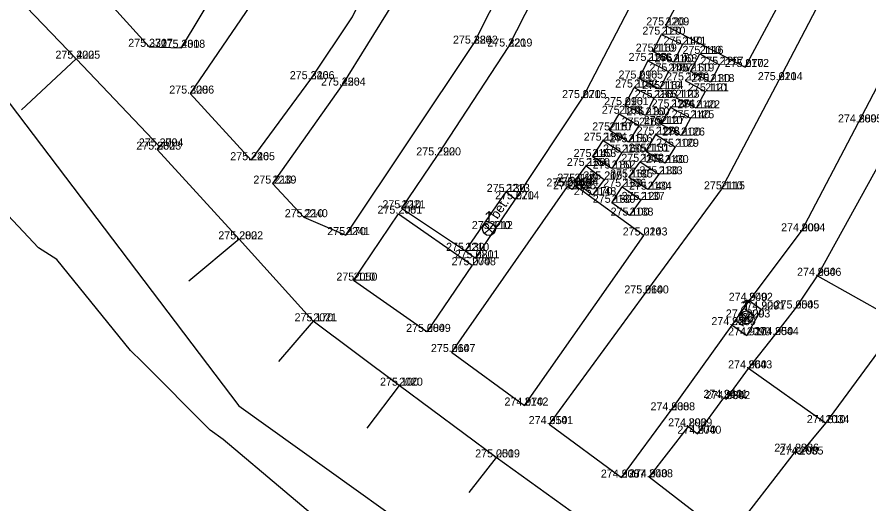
# Model space of a CAD drawing. Extents: x -776701 to -776081, y -974398 to -973771.
# Drawn here: x -776439.32 to -776412.71, y -974187.69 to -974172.49 of the extents above; entities that cross this region are included whole.
import ezdxf

# ---------------------------------------------------------------- set-up
doc = ezdxf.new("R2010")
doc.units = 0
for name, color, linetype in [('1 Body-bod', 7, 'Continuous'), ('10 Silnice-chodniky', 7, 'Continuous'), ('11 Rozhrani-nezpev zpev schody', 7, 'Continuous'), ('2 Body-cislo', 7, 'Continuous'), ('3 Body-vyska', 7, 'Continuous'), ('40 Popis-povrch', 7, 'Continuous'), ('58 Mobiliar', 7, 'Continuous'), ('7 Ploty', 7, 'Continuous'), ('Hranice parcel', 7, 'Continuous')]:
    doc.layers.add(name, color=color, linetype=linetype)

msp = doc.modelspace()

# ---------------------------------------------------------------- linework, layer by layer
at = {"layer": '1 Body-bod'}
for p, q in [((-776419.07, -974172.75), (-776419.07, -974172.75)), ((-776419.19, -974173.04), (-776419.19, -974173.04)), ((-776435.2, -974173.42), (-776435.2, -974173.42)), ((-776425.05, -974173.32), (-776425.05, -974173.32)), ((-776423.97, -974173.41), (-776423.97, -974173.41)), ((-776418.54, -974173.35), (-776418.54, -974173.35)), ((-776434.19, -974173.45), (-776434.19, -974173.45)), ((-776419.46, -974173.57), (-776419.46, -974173.57)), ((-776418, -974173.64), (-776418, -974173.64)), ((-776437.47, -974173.79), (-776437.47, -974173.79)), ((-776419.62, -974173.86), (-776419.62, -974173.86)), ((-776418.82, -974173.9), (-776418.82, -974173.9)), ((-776418.98, -974174.19), (-776418.98, -974174.19)), ((-776418.29, -974174.19), (-776418.29, -974174.19)), ((-776417.38, -974173.98), (-776417.38, -974173.98)), ((-776416.58, -974174.05), (-776416.58, -974174.05)), ((-776430.15, -974174.43), (-776430.15, -974174.43)), ((-776419.89, -974174.41), (-776419.89, -974174.41)), ((-776418.45, -974174.47), (-776418.45, -974174.47)), ((-776415.53, -974174.46), (-776415.53, -974174.46)), ((-776429.18, -974174.63), (-776429.18, -974174.63)), ((-776420.05, -974174.69), (-776420.05, -974174.69)), ((-776419.26, -974174.74), (-776419.26, -974174.74)), ((-776417.66, -974174.52), (-776417.66, -974174.52)), ((-776433.91, -974174.88), (-776433.91, -974174.88)), ((-776421.66, -974175.02), (-776421.66, -974175.02)), ((-776419.43, -974175.02), (-776419.43, -974175.02)), ((-776418.75, -974175.01), (-776418.75, -974175.01)), ((-776417.83, -974174.81), (-776417.83, -974174.81)), ((-776420.34, -974175.24), (-776420.34, -974175.24)), ((-776420.52, -974175.51), (-776420.52, -974175.51)), ((-776419.69, -974175.56), (-776419.69, -974175.56)), ((-776418.9, -974175.31), (-776418.9, -974175.31)), ((-776418.11, -974175.34), (-776418.11, -974175.34)), ((-776418.29, -974175.65), (-776418.29, -974175.65)), ((-776413.04, -974175.78), (-776413.04, -974175.78)), ((-776420.82, -974176.03), (-776420.82, -974176.03)), ((-776419.9, -974175.88), (-776419.9, -974175.88)), ((-776419.21, -974175.83), (-776419.21, -974175.83)), ((-776421.02, -974176.35), (-776421.02, -974176.35)), ((-776419.37, -974176.16), (-776419.37, -974176.16)), ((-776418.58, -974176.19), (-776418.58, -974176.19)), ((-776434.87, -974176.53), (-776434.87, -974176.53)), ((-776420.22, -974176.4), (-776420.22, -974176.4)), ((-776418.77, -974176.54), (-776418.77, -974176.54)), ((-776434.94, -974176.63), (-776434.94, -974176.63)), ((-776426.2, -974176.81), (-776426.2, -974176.81)), ((-776421.35, -974176.86), (-776421.35, -974176.86)), ((-776420.43, -974176.72), (-776420.43, -974176.72)), ((-776419.68, -974176.69), (-776419.68, -974176.69)), ((-776432.01, -974176.96), (-776432.01, -974176.96)), ((-776421.55, -974177.14), (-776421.55, -974177.14)), ((-776419.86, -974177.01), (-776419.86, -974177.01)), ((-776419.09, -974177.05), (-776419.09, -974177.05)), ((-776420.75, -974177.22), (-776420.75, -974177.22)), ((-776419.28, -974177.4), (-776419.28, -974177.4)), ((-776431.34, -974177.69), (-776431.34, -974177.69)), ((-776421.91, -974177.63), (-776421.91, -974177.63)), ((-776420.98, -974177.56), (-776420.98, -974177.56)), ((-776420.21, -974177.5), (-776420.21, -974177.5)), ((-776424.05, -974177.95), (-776424.05, -974177.95)), ((-776422.14, -974177.78), (-776422.14, -974177.78)), ((-776421.98, -974177.87), (-776421.98, -974177.87)), ((-776421.9, -974177.75), (-776421.9, -974177.75)), ((-776420.42, -974177.79), (-776420.42, -974177.79)), ((-776419.62, -974177.88), (-776419.62, -974177.88)), ((-776417.33, -974177.87), (-776417.33, -974177.87)), ((-776423.75, -974178.18), (-776423.75, -974178.18)), ((-776421.35, -974178.05), (-776421.35, -974178.05)), ((-776419.84, -974178.2), (-776419.84, -974178.2)), ((-776427.31, -974178.46), (-776427.31, -974178.46)), ((-776420.75, -974178.29), (-776420.75, -974178.29)), ((-776430.36, -974178.74), (-776430.36, -974178.74)), ((-776427.41, -974178.63), (-776427.41, -974178.63)), ((-776420.19, -974178.69), (-776420.19, -974178.69)), ((-776424.58, -974179.11), (-776424.58, -974179.11)), ((-776414.82, -974179.18), (-776414.82, -974179.18)), ((-776432.38, -974179.43), (-776432.38, -974179.43)), ((-776429.05, -974179.3), (-776429.05, -974179.3)), ((-776419.75, -974179.31), (-776419.75, -974179.31)), ((-776425.32, -974179.79), (-776425.32, -974179.79)), ((-776425, -974180.02), (-776425, -974180.02)), ((-776425.11, -974180.24), (-776425.11, -974180.24)), ((-776414.32, -974180.57), (-776414.32, -974180.57)), ((-776428.81, -974180.72), (-776428.81, -974180.72)), ((-776419.71, -974181.12), (-776419.71, -974181.12)), ((-776416.46, -974181.35), (-776416.46, -974181.35)), ((-776416.08, -974181.62), (-776416.08, -974181.62)), ((-776415.01, -974181.59), (-776415.01, -974181.59)), ((-776416.54, -974181.87), (-776416.54, -974181.87)), ((-776430.07, -974181.99), (-776430.07, -974181.99)), ((-776416.99, -974182.11), (-776416.99, -974182.11)), ((-776426.52, -974182.32), (-776426.52, -974182.32)), ((-776416.53, -974182.43), (-776416.53, -974182.43)), ((-776415.65, -974182.42), (-776415.65, -974182.42)), ((-776425.75, -974182.95), (-776425.75, -974182.95)), ((-776416.48, -974183.46), (-776416.48, -974183.46)), ((-776427.39, -974184), (-776427.39, -974184)), ((-776417.25, -974184.38), (-776417.25, -974184.38)), ((-776417.17, -974184.42), (-776417.17, -974184.42)), ((-776423.47, -974184.62), (-776423.47, -974184.62)), ((-776418.89, -974184.77), (-776418.89, -974184.77)), ((-776422.7, -974185.2), (-776422.7, -974185.2)), ((-776418.35, -974185.27), (-776418.35, -974185.27)), ((-776414.07, -974185.17), (-776414.07, -974185.17)), ((-776418.07, -974185.5), (-776418.07, -974185.5)), ((-776415.02, -974186.06), (-776415.02, -974186.06)), ((-776414.88, -974186.15), (-776414.88, -974186.15)), ((-776424.36, -974186.24), (-776424.36, -974186.24)), ((-776420.44, -974186.87), (-776420.44, -974186.87)), ((-776419.58, -974186.86), (-776419.58, -974186.86))]:
    msp.add_line(p, q, dxfattribs=at)
at = {"layer": '10 Silnice-chodniky'}
for points in [[(-776425.32, -974179.79), (-776425, -974180.02), (-776423.75, -974178.18)], [(-776416.99, -974182.11), (-776416.53, -974182.43), (-776416.08, -974181.62), (-776416.46, -974181.35)]]:
    msp.add_lwpolyline(points, dxfattribs=at)
at = {"layer": '11 Rozhrani-nezpev zpev schody'}
for points in [[(-776418.82, -974173.9), (-776419.46, -974173.57), (-776419.19, -974173.04), (-776418.54, -974173.35), (-776418.82, -974173.9)], [(-776418, -974173.64), (-776417.38, -974173.98), (-776417.66, -974174.52), (-776418.29, -974174.19), (-776418, -974173.64)], [(-776419.26, -974174.74), (-776419.89, -974174.41), (-776419.62, -974173.86), (-776418.98, -974174.19), (-776419.26, -974174.74)], [(-776418.45, -974174.47), (-776417.83, -974174.81), (-776418.11, -974175.34), (-776418.75, -974175.01)], [(-776419.69, -974175.56), (-776420.34, -974175.24), (-776420.05, -974174.69), (-776419.43, -974175.02), (-776419.69, -974175.56)], [(-776420.22, -974176.4), (-776420.82, -974176.03), (-776420.52, -974175.51), (-776419.9, -974175.88), (-776420.22, -974176.4)], [(-776418.9, -974175.31), (-776418.29, -974175.65), (-776418.58, -974176.19), (-776419.21, -974175.83), (-776418.9, -974175.31)], [(-776420.75, -974177.22), (-776421.35, -974176.86), (-776421.02, -974176.35), (-776420.43, -974176.72), (-776420.75, -974177.22)], [(-776419.37, -974176.16), (-776418.77, -974176.54), (-776419.09, -974177.05), (-776419.68, -974176.69), (-776419.37, -974176.16)], [(-776421.35, -974178.05), (-776421.91, -974177.63), (-776421.55, -974177.14), (-776420.98, -974177.56), (-776421.35, -974178.05)], [(-776419.86, -974177.01), (-776419.28, -974177.4), (-776419.62, -974177.88), (-776420.21, -974177.5), (-776419.86, -974177.01)], [(-776420.42, -974177.79), (-776419.84, -974178.2), (-776420.19, -974178.69), (-776420.75, -974178.29), (-776420.42, -974177.79)]]:
    msp.add_lwpolyline(points, dxfattribs=at)
at = {"layer": '58 Mobiliar'}
for p, q in [((-776424.58, -974178.56), (-776424.68, -974178.66)), ((-776424.58, -974178.909), (-776424.58, -974178.56)), ((-776424.58, -974178.56), (-776424.48, -974178.66)), ((-776424.58, -974179.11), (-776424.723, -974178.968)), ((-776424.58, -974179.11), (-776424.438, -974178.968)), ((-776424.58, -974179.11), (-776424.723, -974179.253)), ((-776424.58, -974179.11), (-776424.58, -974179.11)), ((-776424.58, -974179.11), (-776424.438, -974179.253)), ((-776416.54, -974181.32), (-776416.64, -974181.42)), ((-776416.54, -974181.669), (-776416.54, -974181.32)), ((-776416.54, -974181.32), (-776416.44, -974181.42)), ((-776416.54, -974181.87), (-776416.682, -974181.728)), ((-776416.54, -974181.87), (-776416.682, -974182.013)), ((-776416.54, -974181.87), (-776416.397, -974181.728)), ((-776416.54, -974181.87), (-776416.54, -974181.87)), ((-776416.54, -974181.87), (-776416.397, -974182.013))]:
    msp.add_line(p, q, dxfattribs=at)
for centre in [(-776424.58, -974179.11), (-776416.54, -974181.87)]:
    msp.add_circle(centre, 0.202, dxfattribs=at)
at = {"layer": '7 Ploty'}
for p, q in [((-776437.47, -974173.79), (-776439.178, -974175.39)), ((-776432.38, -974179.43), (-776433.951, -974180.734)), ((-776414.32, -974180.57), (-776411.75, -974182.02)), ((-776430.07, -974181.99), (-776431.16, -974183.244)), ((-776414.07, -974185.17), (-776416.48, -974183.46)), ((-776427.39, -974184), (-776428.392, -974185.327)), ((-776424.36, -974186.24), (-776425.214, -974187.339))]:
    msp.add_line(p, q, dxfattribs=at)
for points in [[(-776432.01, -974176.96), (-776430.15, -974174.43), (-776428.84, -974172.48), (-776426.21, -974167.13), (-776424.02, -974162.64), (-776420.72, -974155.89), (-776417.48, -974149.18), (-776414.84, -974143.58), (-776412.06, -974137.85), (-776410.96, -974135.57), (-776413.49, -974134.39), (-776415.66, -974138.85), (-776417.85, -974143.38), (-776420.08, -974148.01), (-776422.17, -974152.39), (-776424.4, -974156.87), (-776426.57, -974161.43), (-776428.76, -974165.89), (-776429.88, -974168.2), (-776431.18, -974170.86), (-776433.91, -974174.88), (-776432.01, -974176.96)], [(-776431.34, -974177.69), (-776430.36, -974178.74), (-776429.05, -974179.3), (-776425.05, -974173.32), (-776421.66, -974166.59), (-776420.59, -974164.45), (-776417.2, -974157.6), (-776414.58, -974152.44), (-776411.04, -974145.26), (-776408.67, -974140.55), (-776407.14, -974137.4), (-776409.65, -974136.23), (-776410.76, -974138.44), (-776413.59, -974144.07), (-776416.31, -974149.56), (-776419.81, -974156.48), (-776423.16, -974163.16), (-776425.35, -974167.56), (-776426.48, -974169.85), (-776427.57, -974172.05), (-776429.18, -974174.63), (-776431.34, -974177.69)], [(-776431.15, -974168.39), (-776429.66, -974165.41), (-776428.19, -974162.28), (-776425.9, -974157.45), (-776423.75, -974152.89), (-776421.33, -974147.81), (-776419.08, -974142.85), (-776416.94, -974138.29), (-776419.5, -974137.14), (-776421.61, -974141.66), (-776423.21, -974145.07), (-776425.27, -974149.44), (-776427.38, -974153.95), (-776429.62, -974158.72), (-776430.48, -974160.61), (-776432.15, -974164.11), (-776433.43, -974166.78), (-776434.67, -974168.81), (-776435.8, -974170.57), (-776436.61, -974171.85), (-776435.2, -974173.42), (-776434.19, -974173.45), (-776431.15, -974168.39)], [(-776410.02, -974178.63), (-776411.75, -974182.02), (-776414.07, -974185.17), (-776414.88, -974186.15), (-776415.02, -974186.06), (-776417.11, -974188.76), (-776419.58, -974186.86), (-776418.35, -974185.27), (-776418.07, -974185.5), (-776417.25, -974184.38), (-776417.17, -974184.42), (-776416.48, -974183.46), (-776415.65, -974182.42), (-776415.01, -974181.59), (-776414.32, -974180.57), (-776411.96, -974176.29), (-776407.95, -974168.57), (-776405.03, -974163.01), (-776402.53, -974158.19), (-776400.94, -974155.22), (-776397.47, -974148.58), (-776394.68, -974143.21), (-776392.14, -974144.47)], [(-776415.33, -974192.73), (-776418.2, -974190.66), (-776421.23, -974188.49), (-776424.36, -974186.24), (-776427.39, -974184), (-776430.07, -974181.99), (-776432.38, -974179.43), (-776434.94, -974176.63), (-776434.87, -974176.53), (-776437.47, -974173.79), (-776440.34, -974170.82), (-776442.68, -974168.36), (-776445.15, -974165.67), (-776446.94, -974163.01), (-776451.45, -974156.97), (-776456.49, -974149.91), (-776458.27, -974147.5), (-776460.71, -974144.17), (-776461.87, -974145.07)], [(-776412.09, -974159.27), (-776414.44, -974163.91), (-776416.71, -974168.32), (-776417.85, -974170.49), (-776419.07, -974172.75), (-776416.58, -974174.05)], [(-776416.58, -974174.05), (-776414.17, -974169.55), (-776410.74, -974162.85)], [(-776411.46, -974166.68), (-776415.53, -974174.46), (-776417.33, -974177.87), (-776419.71, -974181.12), (-776422.7, -974185.2), (-776420.44, -974186.87)], [(-776420.44, -974186.87), (-776418.89, -974184.77), (-776416.99, -974182.11), (-776416.46, -974181.35), (-776414.82, -974179.18), (-776413.04, -974175.78), (-776408.98, -974168.02)], [(-776425.32, -974179.79), (-776424.05, -974177.95), (-776423.75, -974178.18), (-776421.66, -974175.02), (-776420.33, -974172.46), (-776419.18, -974170.22), (-776421.69, -974168.93), (-776423.97, -974173.41), (-776426.2, -974176.81), (-776427.31, -974178.46), (-776425.32, -974179.79)], [(-776423.47, -974184.62), (-776419.75, -974179.31), (-776421.9, -974177.75), (-776421.98, -974177.87), (-776422.14, -974177.78), (-776425.75, -974182.95), (-776423.47, -974184.62)], [(-776425.11, -974180.24), (-776426.52, -974182.32), (-776428.81, -974180.72), (-776427.41, -974178.63), (-776425.11, -974180.24)]]:
    msp.add_lwpolyline(points, dxfattribs=at)
at = {"layer": 'Hranice parcel'}
for points in [[(-776425.04, -974191.8), (-776425.52, -974191.53), (-776428.6, -974189.19), (-776429.03, -974188.93), (-776432.88, -974185.68), (-776433.29, -974185.39), (-776435.41, -974183.26), (-776435.78, -974182.9), (-776438.08, -974180.06), (-776438.65, -974179.7), (-776443.59, -974174.45), (-776443.94, -974174.06), (-776448.63, -974169.08), (-776448.94, -974168.67), (-776452.87, -974162.91), (-776453.18, -974162.44), (-776459.11, -974154.55), (-776459.39, -974154.1), (-776461.5, -974151.3), (-776461.83, -974150.84), (-776461.03, -974150.2)], [(-776441.53, -974172.59), (-776432.39, -974184.63), (-776424.22, -974190.48)]]:
    msp.add_lwpolyline(points, dxfattribs=at)

# ---------------------------------------------------------------- texts
at = {"layer": '2 Body-cislo'}
for s, p in [('2209', (-776419.07, -974172.75)), ('2170', (-776419.19, -974173.04)), ('2317', (-776435.2, -974173.42)), ('2242', (-776425.05, -974173.32)), ('2219', (-776423.97, -974173.41)), ('2171', (-776418.54, -974173.35)), ('2318', (-776434.19, -974173.45)), ('2169', (-776419.46, -974173.57)), ('2116', (-776418, -974173.64)), ('2025', (-776437.47, -974173.79)), ('2166', (-776419.62, -974173.86)), ('2168', (-776418.82, -974173.9)), ('2167', (-776418.98, -974174.19)), ('2119', (-776418.29, -974174.19)), ('2117', (-776417.38, -974173.98)), ('2172', (-776416.58, -974174.05)), ('2266', (-776430.15, -974174.43)), ('2165', (-776419.89, -974174.41)), ('2120', (-776418.45, -974174.47)), ('2114', (-776415.53, -974174.46)), ('2264', (-776429.18, -974174.63)), ('2162', (-776420.05, -974174.69)), ('2164', (-776419.26, -974174.74)), ('2118', (-776417.66, -974174.52)), ('2286', (-776433.91, -974174.88)), ('2123', (-776418.75, -974175.01)), ('2121', (-776417.83, -974174.81)), ('2215', (-776421.66, -974175.02)), ('2161', (-776420.34, -974175.24)), ('2163', (-776419.43, -974175.02)), ('2158', (-776420.52, -974175.51)), ('2124', (-776418.9, -974175.31)), ('2122', (-776418.11, -974175.34)), ('2160', (-776419.69, -974175.56)), ('2125', (-776418.29, -974175.65)), ('2095', (-776413.04, -974175.78)), ('2157', (-776420.82, -974176.03)), ('2159', (-776419.9, -974175.88)), ('2127', (-776419.21, -974175.83)), ('2128', (-776419.37, -974176.16)), ('2126', (-776418.58, -974176.19)), ('2024', (-776434.87, -974176.53)), ('2154', (-776421.02, -974176.35)), ('2156', (-776420.22, -974176.4)), ('2129', (-776418.77, -974176.54)), ('2023', (-776434.94, -974176.63)), ('2220', (-776426.2, -974176.81)), ('2153', (-776421.35, -974176.86)), ('2155', (-776420.43, -974176.72)), ('2131', (-776419.68, -974176.69)), ('2265', (-776432.01, -974176.96)), ('2150', (-776421.55, -974177.14)), ('2132', (-776419.86, -974177.01)), ('2130', (-776419.09, -974177.05)), ('2152', (-776420.75, -974177.22)), ('2133', (-776419.28, -974177.4)), ('2149', (-776421.91, -974177.63)), ('2151', (-776420.98, -974177.56)), ('2135', (-776420.21, -974177.5)), ('2239', (-776431.34, -974177.69)), ('2146', (-776422.14, -974177.78)), ('2145', (-776421.98, -974177.87)), ('2144', (-776421.9, -974177.75)), ('2136', (-776420.42, -974177.79)), ('2134', (-776419.62, -974177.88)), ('2115', (-776417.33, -974177.87)), ('2213', (-776424.05, -974177.95)), ('2214', (-776423.75, -974178.18)), ('2148', (-776421.35, -974178.05)), ('2137', (-776419.84, -974178.2)), ('2221', (-776427.31, -974178.46)), ('2139', (-776420.75, -974178.29)), ('2240', (-776430.36, -974178.74)), ('2051', (-776427.41, -974178.63)), ('2138', (-776420.19, -974178.69)), ('2212', (-776424.58, -974179.11)), ('2094', (-776414.82, -974179.18)), ('2022', (-776432.38, -974179.43)), ('2241', (-776429.05, -974179.3)), ('2143', (-776419.75, -974179.31)), ('2210', (-776425.32, -974179.79)), ('2211', (-776425, -974180.02)), ('2048', (-776425.11, -974180.24)), ('2046', (-776414.32, -974180.57)), ('2050', (-776428.81, -974180.72)), ('2140', (-776419.71, -974181.12)), ('2092', (-776416.46, -974181.35)), ('2091', (-776416.08, -974181.62)), ('2045', (-776415.01, -974181.59)), ('2093', (-776416.54, -974181.87)), ('2021', (-776430.07, -974181.99)), ('2089', (-776416.99, -974182.11)), ('2049', (-776426.52, -974182.32)), ('2090', (-776416.53, -974182.43)), ('2044', (-776415.65, -974182.42)), ('2147', (-776425.75, -974182.95)), ('2043', (-776416.48, -974183.46)), ('2020', (-776427.39, -974184)), ('2041', (-776417.25, -974184.38)), ('2042', (-776417.17, -974184.42)), ('2142', (-776423.47, -974184.62)), ('2088', (-776418.89, -974184.77)), ('2141', (-776422.7, -974185.2)), ('2039', (-776418.35, -974185.27)), ('2034', (-776414.07, -974185.17)), ('2040', (-776418.07, -974185.5)), ('2036', (-776415.02, -974186.06)), ('2035', (-776414.88, -974186.15)), ('2019', (-776424.36, -974186.24)), ('2087', (-776420.44, -974186.87)), ('2038', (-776419.58, -974186.86))]:
    msp.add_text(s, height=0.25, dxfattribs=at).set_placement(p)
at = {"layer": '3 Body-vyska'}
for s, p in [('275.120', (-776419.67, -974172.75)), ('275.120', (-776419.79, -974173.04)), ('275.370', (-776435.848, -974173.42)), ('275.380', (-776425.707, -974173.32)), ('275.320', (-776424.634, -974173.41)), ('275.140', (-776419.129, -974173.35)), ('275.400', (-776434.835, -974173.45)), ('275.110', (-776419.998, -974173.57)), ('275.110', (-776418.538, -974173.64)), ('275.420', (-776438.122, -974173.79)), ('275.130', (-776420.222, -974173.86)), ('275.140', (-776419.409, -974173.9)), ('275.140', (-776419.569, -974174.19)), ('275.150', (-776418.886, -974174.19)), ('275.120', (-776417.98, -974173.98)), ('275.070', (-776417.219, -974174.05)), ('275.340', (-776430.803, -974174.43)), ('275.090', (-776420.535, -974174.41)), ('275.120', (-776419.05, -974174.47)), ('275.020', (-776416.185, -974174.46)), ('275.450', (-776429.828, -974174.63)), ('275.100', (-776420.643, -974174.69)), ('275.110', (-776419.798, -974174.74)), ('275.130', (-776418.262, -974174.52)), ('275.300', (-776434.567, -974174.88)), ('275.110', (-776419.288, -974175.01)), ('275.110', (-776418.368, -974174.81)), ('275.070', (-776422.299, -974175.02)), ('275.090', (-776420.985, -974175.24)), ('275.130', (-776420.032, -974175.02)), ('275.110', (-776421.058, -974175.51)), ('275.130', (-776419.502, -974175.31)), ('275.140', (-776418.699, -974175.34)), ('275.130', (-776420.292, -974175.56)), ('275.140', (-776418.879, -974175.65)), ('274.880', (-776413.682, -974175.78)), ('275.110', (-776421.358, -974176.03)), ('275.110', (-776420.438, -974175.88)), ('275.110', (-776419.748, -974175.83)), ('275.120', (-776419.97, -974176.16)), ('275.100', (-776419.173, -974176.19)), ('275.370', (-776435.518, -974176.53)), ('275.130', (-776421.622, -974176.35)), ('275.150', (-776420.816, -974176.4)), ('275.100', (-776419.363, -974176.54)), ('275.380', (-776435.597, -974176.63)), ('275.290', (-776426.852, -974176.81)), ('275.140', (-776421.939, -974176.86)), ('275.160', (-776421.019, -974176.72)), ('275.110', (-776420.218, -974176.69)), ('275.240', (-776432.662, -974176.96)), ('275.130', (-776422.152, -974177.14)), ('275.140', (-776420.449, -974177.01)), ('275.140', (-776419.679, -974177.05)), ('275.180', (-776421.343, -974177.22)), ('275.130', (-776419.882, -974177.4)), ('275.110', (-776422.448, -974177.63)), ('275.200', (-776421.635, -974177.56)), ('275.160', (-776420.799, -974177.5)), ('275.210', (-776431.94, -974177.69)), ('275.080', (-776422.789, -974177.78)), ('275.120', (-776422.58, -974177.87)), ('275.120', (-776422.5, -974177.75)), ('275.180', (-776421.013, -974177.79)), ('275.140', (-776420.209, -974177.88)), ('275.110', (-776417.868, -974177.87)), ('275.130', (-776424.652, -974177.95)), ('275.070', (-776424.389, -974178.18)), ('275.170', (-776421.934, -974178.05)), ('275.120', (-776420.44, -974178.2)), ('275.210', (-776427.91, -974178.46)), ('275.160', (-776421.339, -974178.29)), ('275.210', (-776430.96, -974178.74)), ('275.200', (-776428.065, -974178.63)), ('275.100', (-776420.783, -974178.69)), ('275.110', (-776425.118, -974179.11)), ('274.900', (-776415.458, -974179.18)), ('275.280', (-776433.035, -974179.43)), ('275.170', (-776429.634, -974179.3)), ('275.020', (-776420.405, -974179.31)), ('275.130', (-776425.922, -974179.79)), ('275.080', (-776425.649, -974180.02)), ('275.070', (-776425.749, -974180.24)), ('274.950', (-776414.961, -974180.57)), ('275.110', (-776429.348, -974180.72)), ('275.060', (-776420.355, -974181.12)), ('274.940', (-776417.094, -974181.35)), ('274.920', (-776416.725, -974181.62)), ('275.050', (-776415.662, -974181.59)), ('274.920', (-776417.185, -974181.87)), ('275.170', (-776430.654, -974181.99)), ('274.920', (-776417.635, -974182.11)), ('275.080', (-776427.169, -974182.32)), ('274.910', (-776417.113, -974182.43)), ('274.950', (-776416.291, -974182.42)), ('275.060', (-776426.395, -974182.95)), ('274.960', (-776417.114, -974183.46)), ('275.100', (-776427.983, -974184)), ('274.940', (-776417.884, -974184.38)), ('274.930', (-776417.817, -974184.42)), ('274.970', (-776424.098, -974184.62)), ('274.930', (-776419.537, -974184.77)), ('274.950', (-776423.341, -974185.2)), ('274.890', (-776418.988, -974185.27)), ('274.810', (-776414.657, -974185.17)), ('274.970', (-776418.698, -974185.5)), ('274.830', (-776415.671, -974186.06)), ('274.790', (-776415.508, -974186.15)), ('275.050', (-776425.012, -974186.24)), ('274.930', (-776421.087, -974186.87)), ('274.940', (-776420.214, -974186.86))]:
    msp.add_text(s, height=0.25, dxfattribs=at).set_placement(p)
at = {"layer": '40 Popis-povrch'}
for rotation, p in [(55.8099, (-776424.318, -974178.822)), (55.1093, (-776416.653, -974182.178))]:
    msp.add_text('bet.', height=0.3, rotation=rotation, dxfattribs=at).set_placement(p)

doc.saveas('drawing.dxf')
